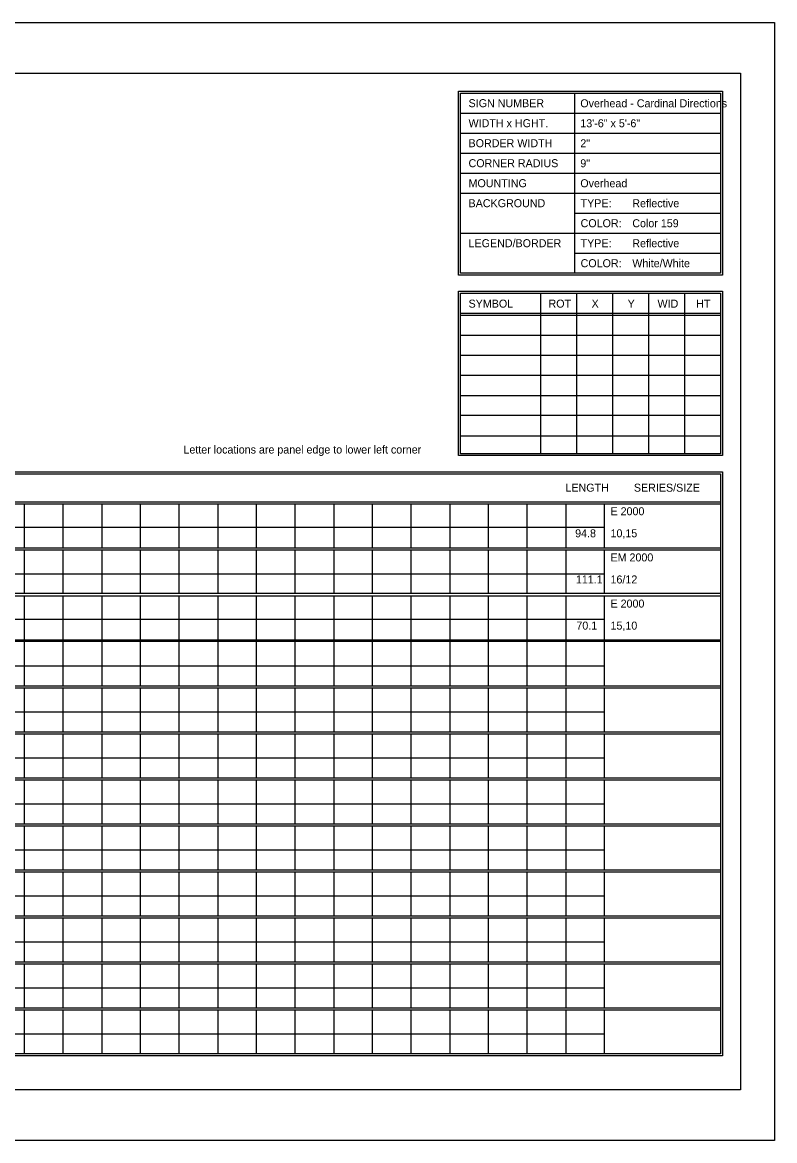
# Model space of a CAD drawing. Extents: x 1806251 to 1809821, y 414895 to 422886.
# Drawn here: x 1809679.34 to 1809684.89, y 415075.97 to 415084.23 of the extents above; entities that cross this region are included whole.
import ezdxf

# ---------------------------------------------------------------- set-up
doc = ezdxf.new("R2010")
doc.units = 0
doc.layers.add('GSSHT', color=7, linetype='Continuous')

msp = doc.modelspace()

# ---------------------------------------------------------------- linework, layer by layer
at = {"layer": 'GSSHT'}
for p, q in [((1809672.1349, 415084.2262), (1809684.8891, 415084.2262)), ((1809684.8891, 415084.2262), (1809684.8891, 415075.9725)), ((1809683.4126, 415083.7035), (1809683.4126, 415082.3747)), ((1809682.571, 415083.5559), (1809684.4905, 415083.5559)), ((1809682.571, 415083.4082), (1809684.4905, 415083.4082)), ((1809682.571, 415083.2606), (1809684.4905, 415083.2606)), ((1809682.571, 415083.1129), (1809684.4905, 415083.1129)), ((1809682.571, 415082.9653), (1809684.4905, 415082.9653)), ((1809683.4126, 415082.8176), (1809684.4905, 415082.8176)), ((1809682.571, 415082.67), (1809684.4905, 415082.67)), ((1809683.4126, 415082.5223), (1809684.4905, 415082.5223)), ((1809683.1616, 415082.227), (1809683.1616, 415081.0428)), ((1809683.4274, 415082.227), (1809683.4274, 415081.0428)), ((1809683.6931, 415082.227), (1809683.6931, 415081.0428)), ((1809683.9589, 415082.227), (1809683.9589, 415081.0428)), ((1809684.2247, 415082.227), (1809684.2247, 415081.0428)), ((1809682.571, 415082.0794), (1809684.4905, 415082.0794)), ((1809682.571, 415082.0646), (1809684.4905, 415082.0646)), ((1809682.571, 415081.9169), (1809684.4905, 415081.9169)), ((1809682.571, 415081.7693), (1809684.4905, 415081.7693)), ((1809682.571, 415081.6216), (1809684.4905, 415081.6216)), ((1809682.571, 415081.471), (1809684.4905, 415081.471)), ((1809682.571, 415081.3263), (1809684.4905, 415081.3263)), ((1809682.571, 415081.1757), (1809684.4905, 415081.1757)), ((1809672.7816, 415080.6885), (1809684.4905, 415080.6885)), ((1809672.7816, 415080.6737), (1809684.4905, 415080.6737)), ((1809679.3492, 415080.6737), (1809679.3492, 415080.3489)), ((1809679.6357, 415080.6737), (1809679.6357, 415080.3489)), ((1809679.9221, 415080.6737), (1809679.9221, 415080.3489)), ((1809680.2056, 415080.6737), (1809680.2056, 415080.3489)), ((1809680.492, 415080.6737), (1809680.492, 415080.3489)), ((1809680.7785, 415080.6737), (1809680.7785, 415080.3489)), ((1809681.062, 415080.6737), (1809681.062, 415080.3489)), ((1809681.3484, 415080.6737), (1809681.3484, 415080.3489)), ((1809681.6349, 415080.6737), (1809681.6349, 415080.3489)), ((1809681.9184, 415080.6737), (1809681.9184, 415080.3489)), ((1809682.2048, 415080.6737), (1809682.2048, 415080.3489)), ((1809682.4913, 415080.6737), (1809682.4913, 415080.3489)), ((1809682.7747, 415080.6737), (1809682.7747, 415080.3489)), ((1809683.0612, 415080.6737), (1809683.0612, 415080.3489)), ((1809683.3476, 415080.6737), (1809683.3476, 415080.3489)), ((1809683.6311, 415080.6737), (1809683.6311, 415080.3489)), ((1809672.7816, 415080.4995), (1809683.6311, 415080.4995)), ((1809672.7816, 415080.3489), (1809684.4905, 415080.3489)), ((1809672.7816, 415080.3341), (1809684.4905, 415080.3341)), ((1809679.3492, 415080.3341), (1809679.3492, 415080.0122)), ((1809679.6357, 415080.3341), (1809679.6357, 415080.0122)), ((1809679.9221, 415080.3341), (1809679.9221, 415080.0122)), ((1809680.2056, 415080.3341), (1809680.2056, 415080.0122)), ((1809680.492, 415080.3341), (1809680.492, 415080.0122)), ((1809680.7785, 415080.3341), (1809680.7785, 415080.0122)), ((1809681.062, 415080.3341), (1809681.062, 415080.0122)), ((1809681.3484, 415080.3341), (1809681.3484, 415080.0122)), ((1809681.6349, 415080.3341), (1809681.6349, 415080.0122)), ((1809681.9184, 415080.3341), (1809681.9184, 415080.0122)), ((1809682.2048, 415080.3341), (1809682.2048, 415080.0122)), ((1809682.4913, 415080.3341), (1809682.4913, 415080.0122)), ((1809682.7747, 415080.3341), (1809682.7747, 415080.0122)), ((1809683.0612, 415080.3341), (1809683.0612, 415080.0122)), ((1809683.3476, 415080.3341), (1809683.3476, 415080.0122)), ((1809683.6311, 415080.3341), (1809683.6311, 415080.0122)), ((1809672.7816, 415080.1569), (1809683.6311, 415080.1569)), ((1809672.7816, 415080.0122), (1809684.4905, 415080.0122)), ((1809672.7816, 415079.9945), (1809684.4905, 415079.9945)), ((1809679.3492, 415079.9945), (1809679.3492, 415079.6697)), ((1809679.6357, 415079.9945), (1809679.6357, 415079.6697)), ((1809679.9221, 415079.9945), (1809679.9221, 415079.6697)), ((1809680.2056, 415079.9945), (1809680.2056, 415079.6697)), ((1809680.492, 415079.9945), (1809680.492, 415079.6697)), ((1809680.7785, 415079.9945), (1809680.7785, 415079.6697)), ((1809681.062, 415079.9945), (1809681.062, 415079.6697)), ((1809681.3484, 415079.9945), (1809681.3484, 415079.6697)), ((1809681.6349, 415079.9945), (1809681.6349, 415079.6697)), ((1809681.9184, 415079.9945), (1809681.9184, 415079.6697)), ((1809682.2048, 415079.9945), (1809682.2048, 415079.6697)), ((1809682.4913, 415079.9945), (1809682.4913, 415079.6697)), ((1809682.7747, 415079.9945), (1809682.7747, 415079.6697)), ((1809683.0612, 415079.9945), (1809683.0612, 415079.6697)), ((1809683.3476, 415079.9945), (1809683.3476, 415079.6697)), ((1809683.6311, 415079.9945), (1809683.6311, 415079.6697)), ((1809672.7816, 415079.8203), (1809683.6311, 415079.8203)), ((1809672.7816, 415079.6697), (1809684.4905, 415079.6697)), ((1809672.7816, 415079.6579), (1809684.4905, 415079.6579)), ((1809679.3492, 415079.6579), (1809679.3492, 415079.3301)), ((1809679.6357, 415079.6579), (1809679.6357, 415079.3301)), ((1809679.9221, 415079.6579), (1809679.9221, 415079.3301)), ((1809680.2056, 415079.6579), (1809680.2056, 415079.3301)), ((1809680.492, 415079.6579), (1809680.492, 415079.3301)), ((1809680.7785, 415079.6579), (1809680.7785, 415079.3301)), ((1809681.062, 415079.6579), (1809681.062, 415079.3301)), ((1809681.3484, 415079.6579), (1809681.3484, 415079.3301)), ((1809681.6349, 415079.6579), (1809681.6349, 415079.3301)), ((1809681.9184, 415079.6579), (1809681.9184, 415079.3301)), ((1809682.2048, 415079.6579), (1809682.2048, 415079.3301)), ((1809682.4913, 415079.6579), (1809682.4913, 415079.3301)), ((1809682.7747, 415079.6579), (1809682.7747, 415079.3301)), ((1809683.0612, 415079.6579), (1809683.0612, 415079.3301)), ((1809683.3476, 415079.6579), (1809683.3476, 415079.3301)), ((1809683.6311, 415079.6579), (1809683.6311, 415079.3301)), ((1809672.7816, 415079.4777), (1809683.6311, 415079.4777)), ((1809672.7816, 415079.3301), (1809684.4905, 415079.3301)), ((1809672.7816, 415079.3153), (1809684.4905, 415079.3153)), ((1809679.3492, 415079.3153), (1809679.3492, 415078.9905)), ((1809679.6357, 415079.3153), (1809679.6357, 415078.9905)), ((1809679.9221, 415079.3153), (1809679.9221, 415078.9905)), ((1809680.2056, 415079.3153), (1809680.2056, 415078.9905)), ((1809680.492, 415079.3153), (1809680.492, 415078.9905)), ((1809680.7785, 415079.3153), (1809680.7785, 415078.9905)), ((1809681.062, 415079.3153), (1809681.062, 415078.9905)), ((1809681.3484, 415079.3153), (1809681.3484, 415078.9905)), ((1809681.6349, 415079.3153), (1809681.6349, 415078.9905)), ((1809681.9184, 415079.3153), (1809681.9184, 415078.9905)), ((1809682.2048, 415079.3153), (1809682.2048, 415078.9905)), ((1809682.4913, 415079.3153), (1809682.4913, 415078.9905)), ((1809682.7747, 415079.3153), (1809682.7747, 415078.9905)), ((1809683.0612, 415079.3153), (1809683.0612, 415078.9905)), ((1809683.3476, 415079.3153), (1809683.3476, 415078.9905)), ((1809683.6311, 415079.3153), (1809683.6311, 415078.9905)), ((1809672.7816, 415079.1381), (1809683.6311, 415079.1381)), ((1809672.7816, 415078.9905), (1809684.4905, 415078.9905)), ((1809672.7816, 415078.9757), (1809684.4905, 415078.9757)), ((1809679.3492, 415078.9757), (1809679.3492, 415078.6509)), ((1809679.6357, 415078.9757), (1809679.6357, 415078.6509)), ((1809679.9221, 415078.9757), (1809679.9221, 415078.6509)), ((1809680.2056, 415078.9757), (1809680.2056, 415078.6509)), ((1809680.492, 415078.9757), (1809680.492, 415078.6509)), ((1809680.7785, 415078.9757), (1809680.7785, 415078.6509)), ((1809681.062, 415078.9757), (1809681.062, 415078.6509)), ((1809681.3484, 415078.9757), (1809681.3484, 415078.6509)), ((1809681.6349, 415078.9757), (1809681.6349, 415078.6509)), ((1809681.9184, 415078.9757), (1809681.9184, 415078.6509)), ((1809682.2048, 415078.9757), (1809682.2048, 415078.6509)), ((1809682.4913, 415078.9757), (1809682.4913, 415078.6509)), ((1809682.7747, 415078.9757), (1809682.7747, 415078.6509)), ((1809683.0612, 415078.9757), (1809683.0612, 415078.6509)), ((1809683.3476, 415078.9757), (1809683.3476, 415078.6509)), ((1809683.6311, 415078.9757), (1809683.6311, 415078.6509)), ((1809672.7816, 415078.7985), (1809683.6311, 415078.7985)), ((1809672.7816, 415078.6509), (1809684.4905, 415078.6509)), ((1809672.7816, 415078.6361), (1809684.4905, 415078.6361)), ((1809679.3492, 415078.6361), (1809679.3492, 415078.3113)), ((1809679.6357, 415078.6361), (1809679.6357, 415078.3113)), ((1809679.9221, 415078.6361), (1809679.9221, 415078.3113)), ((1809680.2056, 415078.6361), (1809680.2056, 415078.3113)), ((1809680.492, 415078.6361), (1809680.492, 415078.3113)), ((1809680.7785, 415078.6361), (1809680.7785, 415078.3113)), ((1809681.062, 415078.6361), (1809681.062, 415078.3113)), ((1809681.3484, 415078.6361), (1809681.3484, 415078.3113)), ((1809681.6349, 415078.6361), (1809681.6349, 415078.3113)), ((1809681.9184, 415078.6361), (1809681.9184, 415078.3113)), ((1809682.2048, 415078.6361), (1809682.2048, 415078.3113)), ((1809682.4913, 415078.6361), (1809682.4913, 415078.3113)), ((1809682.7747, 415078.6361), (1809682.7747, 415078.3113)), ((1809683.0612, 415078.6361), (1809683.0612, 415078.3113)), ((1809683.3476, 415078.6361), (1809683.3476, 415078.3113)), ((1809683.6311, 415078.6361), (1809683.6311, 415078.3113)), ((1809672.7816, 415078.4589), (1809683.6311, 415078.4589)), ((1809672.7816, 415078.3113), (1809684.4905, 415078.3113)), ((1809672.7816, 415078.2965), (1809684.4905, 415078.2965)), ((1809679.3492, 415078.2965), (1809679.3492, 415077.9717)), ((1809679.6357, 415078.2965), (1809679.6357, 415077.9717)), ((1809679.9221, 415078.2965), (1809679.9221, 415077.9717)), ((1809680.2056, 415078.2965), (1809680.2056, 415077.9717)), ((1809680.492, 415078.2965), (1809680.492, 415077.9717)), ((1809680.7785, 415078.2965), (1809680.7785, 415077.9717)), ((1809681.062, 415078.2965), (1809681.062, 415077.9717)), ((1809681.3484, 415078.2965), (1809681.3484, 415077.9717)), ((1809681.6349, 415078.2965), (1809681.6349, 415077.9717)), ((1809681.9184, 415078.2965), (1809681.9184, 415077.9717)), ((1809682.2048, 415078.2965), (1809682.2048, 415077.9717)), ((1809682.4913, 415078.2965), (1809682.4913, 415077.9717)), ((1809682.7747, 415078.2965), (1809682.7747, 415077.9717)), ((1809683.0612, 415078.2965), (1809683.0612, 415077.9717)), ((1809683.3476, 415078.2965), (1809683.3476, 415077.9717)), ((1809683.6311, 415078.2965), (1809683.6311, 415077.9717)), ((1809672.7816, 415078.1193), (1809683.6311, 415078.1193)), ((1809672.7816, 415077.9717), (1809684.4905, 415077.9717)), ((1809672.7816, 415077.9569), (1809684.4905, 415077.9569)), ((1809679.3492, 415077.9569), (1809679.3492, 415077.6321)), ((1809679.6357, 415077.9569), (1809679.6357, 415077.6321)), ((1809679.9221, 415077.9569), (1809679.9221, 415077.6321)), ((1809680.2056, 415077.9569), (1809680.2056, 415077.6321)), ((1809680.492, 415077.9569), (1809680.492, 415077.6321)), ((1809680.7785, 415077.9569), (1809680.7785, 415077.6321)), ((1809681.062, 415077.9569), (1809681.062, 415077.6321)), ((1809681.3484, 415077.9569), (1809681.3484, 415077.6321)), ((1809681.6349, 415077.9569), (1809681.6349, 415077.6321)), ((1809681.9184, 415077.9569), (1809681.9184, 415077.6321)), ((1809682.2048, 415077.9569), (1809682.2048, 415077.6321)), ((1809682.4913, 415077.9569), (1809682.4913, 415077.6321)), ((1809682.7747, 415077.9569), (1809682.7747, 415077.6321)), ((1809683.0612, 415077.9569), (1809683.0612, 415077.6321)), ((1809683.3476, 415077.9569), (1809683.3476, 415077.6321)), ((1809683.6311, 415077.9569), (1809683.6311, 415077.6321)), ((1809672.7816, 415077.7797), (1809683.6311, 415077.7797)), ((1809672.7816, 415077.6321), (1809684.4905, 415077.6321)), ((1809672.7816, 415077.6173), (1809684.4905, 415077.6173)), ((1809679.3492, 415077.6173), (1809679.3492, 415077.2925)), ((1809679.6357, 415077.6173), (1809679.6357, 415077.2925)), ((1809679.9221, 415077.6173), (1809679.9221, 415077.2925)), ((1809680.2056, 415077.6173), (1809680.2056, 415077.2925)), ((1809680.492, 415077.6173), (1809680.492, 415077.2925)), ((1809680.7785, 415077.6173), (1809680.7785, 415077.2925)), ((1809681.062, 415077.6173), (1809681.062, 415077.2925)), ((1809681.3484, 415077.6173), (1809681.3484, 415077.2925)), ((1809681.6349, 415077.6173), (1809681.6349, 415077.2925)), ((1809681.9184, 415077.6173), (1809681.9184, 415077.2925)), ((1809682.2048, 415077.6173), (1809682.2048, 415077.2925)), ((1809682.4913, 415077.6173), (1809682.4913, 415077.2925)), ((1809682.7747, 415077.6173), (1809682.7747, 415077.2925)), ((1809683.0612, 415077.6173), (1809683.0612, 415077.2925)), ((1809683.3476, 415077.6173), (1809683.3476, 415077.2925)), ((1809683.6311, 415077.6173), (1809683.6311, 415077.2925)), ((1809672.7816, 415077.4401), (1809683.6311, 415077.4401)), ((1809672.7816, 415077.2925), (1809684.4905, 415077.2925)), ((1809672.7816, 415077.2777), (1809684.4905, 415077.2777)), ((1809679.3492, 415077.2777), (1809679.3492, 415076.9529)), ((1809679.6357, 415077.2777), (1809679.6357, 415076.9529)), ((1809679.9221, 415077.2777), (1809679.9221, 415076.9529)), ((1809680.2056, 415077.2777), (1809680.2056, 415076.9529)), ((1809680.492, 415077.2777), (1809680.492, 415076.9529)), ((1809680.7785, 415077.2777), (1809680.7785, 415076.9529)), ((1809681.062, 415077.2777), (1809681.062, 415076.9529)), ((1809681.3484, 415077.2777), (1809681.3484, 415076.9529)), ((1809681.6349, 415077.2777), (1809681.6349, 415076.9529)), ((1809681.9184, 415077.2777), (1809681.9184, 415076.9529)), ((1809682.2048, 415077.2777), (1809682.2048, 415076.9529)), ((1809682.4913, 415077.2777), (1809682.4913, 415076.9529)), ((1809682.7747, 415077.2777), (1809682.7747, 415076.9529)), ((1809683.0612, 415077.2777), (1809683.0612, 415076.9529)), ((1809683.3476, 415077.2777), (1809683.3476, 415076.9529)), ((1809683.6311, 415077.2777), (1809683.6311, 415076.9529)), ((1809672.7816, 415077.1005), (1809683.6311, 415077.1005)), ((1809672.7816, 415076.9529), (1809684.4905, 415076.9529)), ((1809672.7816, 415076.9381), (1809684.4905, 415076.9381)), ((1809679.3492, 415076.9381), (1809679.3492, 415076.6133)), ((1809679.6357, 415076.9381), (1809679.6357, 415076.6133)), ((1809679.9221, 415076.9381), (1809679.9221, 415076.6133)), ((1809680.2056, 415076.9381), (1809680.2056, 415076.6133)), ((1809680.492, 415076.9381), (1809680.492, 415076.6133)), ((1809680.7785, 415076.9381), (1809680.7785, 415076.6133)), ((1809681.062, 415076.9381), (1809681.062, 415076.6133)), ((1809681.3484, 415076.9381), (1809681.3484, 415076.6133)), ((1809681.6349, 415076.9381), (1809681.6349, 415076.6133)), ((1809681.9184, 415076.9381), (1809681.9184, 415076.6133)), ((1809682.2048, 415076.9381), (1809682.2048, 415076.6133)), ((1809682.4913, 415076.9381), (1809682.4913, 415076.6133)), ((1809682.7747, 415076.9381), (1809682.7747, 415076.6133)), ((1809683.0612, 415076.9381), (1809683.0612, 415076.6133)), ((1809683.3476, 415076.9381), (1809683.3476, 415076.6133)), ((1809683.6311, 415076.9381), (1809683.6311, 415076.6133)), ((1809672.7816, 415076.7609), (1809683.6311, 415076.7609)), ((1809684.8891, 415075.9725), (1809672.1349, 415075.9725))]:
    msp.add_line(p, q, dxfattribs=at)
for points in [[(1809672.634, 415083.8512), (1809684.6381, 415083.8512), (1809684.6381, 415076.3475), (1809672.634, 415076.3475)], [(1809682.5562, 415083.7183), (1809684.5052, 415083.7183), (1809684.5052, 415082.3599), (1809682.5562, 415082.3599)], [(1809682.571, 415083.7035), (1809684.4905, 415083.7035), (1809684.4905, 415082.3747), (1809682.571, 415082.3747)], [(1809682.5562, 415082.2418), (1809684.5052, 415082.2418), (1809684.5052, 415081.0281), (1809682.5562, 415081.0281)], [(1809682.571, 415082.227), (1809684.4905, 415082.227), (1809684.4905, 415081.0428), (1809682.571, 415081.0428)], [(1809672.7669, 415080.91), (1809684.5052, 415080.91), (1809684.5052, 415076.5985), (1809672.7669, 415076.5985)], [(1809672.7816, 415080.8952), (1809684.4905, 415080.8952), (1809684.4905, 415076.6133), (1809672.7816, 415076.6133)]]:
    msp.add_lwpolyline(points, close=True, dxfattribs=at)

# ---------------------------------------------------------------- texts
for s, height, p in [('SIGN NUMBER', 0.059055, (1809682.63, 415083.6002)), ('Overhead - Cardinal Directions', 0.059025, (1809683.4549, 415083.5994)), ('WIDTH x HGHT.', 0.059055, (1809682.63, 415083.4525)), ('13\'-6" x 5\'-6"', 0.059025, (1809683.4549, 415083.4519)), ('BORDER WIDTH', 0.059055, (1809682.63, 415083.3049)), ('2"', 0.05903, (1809683.4549, 415083.3043)), ('CORNER RADIUS', 0.059055, (1809682.63, 415083.1572)), ('9"', 0.05903, (1809683.4549, 415083.1568)), ('MOUNTING', 0.05906, (1809682.63, 415083.0096)), ('Overhead', 0.05903, (1809683.4549, 415083.0092)), ('BACKGROUND', 0.05906, (1809682.63, 415082.8619)), ('TYPE:', 0.05906, (1809683.4569, 415082.8619)), ('Reflective', 0.05903, (1809683.8386, 415082.8616)), ('COLOR:', 0.05906, (1809683.4569, 415082.7143)), ('Color 159', 0.05903, (1809683.8386, 415082.7141)), ('LEGEND/BORDER', 0.059055, (1809682.63, 415082.5666)), ('TYPE:', 0.05906, (1809683.4569, 415082.5666)), ('Reflective', 0.05903, (1809683.8386, 415082.5665)), ('COLOR:', 0.05906, (1809683.4569, 415082.419)), ('White/White', 0.059025, (1809683.8386, 415082.4189)), ('SYMBOL', 0.05906, (1809682.63, 415082.1207)), ('ROT', 0.05906, (1809683.22, 415082.1207)), ('X', 0.0591, (1809683.538, 415082.1207)), ('Y', 0.0591, (1809683.8041, 415082.1207)), ('WID', 0.05906, (1809684.0246, 415082.1207)), ('HT', 0.05906, (1809684.3102, 415082.1207)), ('Letter locations are panel edge to lower left corner', 0.059025, (1809680.5257, 415081.0437)), ('LENGTH', 0.05906, (1809683.345, 415080.7623)), ('SERIES/SIZE', 0.059061, (1809683.8502, 415080.7623)), ('E 2000', 0.05903, (1809683.6777, 415080.5883)), ('94.8', 0.05903, (1809683.4168, 415080.4257)), ('10,15', 0.05903, (1809683.6777, 415080.4257)), ('EM 2000', 0.05903, (1809683.6777, 415080.2476)), ('111.1', 0.05903, (1809683.4223, 415080.0849)), ('16/12', 0.05903, (1809683.6777, 415080.0849)), ('E 2000', 0.05903, (1809683.6777, 415079.9068)), ('70.1', 0.05903, (1809683.4258, 415079.7442)), ('15,10', 0.05903, (1809683.6777, 415079.7442))]:
    msp.add_text(s, height=height, dxfattribs=at).set_placement(p)

doc.saveas('drawing.dxf')
